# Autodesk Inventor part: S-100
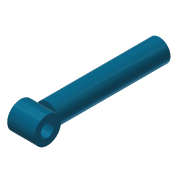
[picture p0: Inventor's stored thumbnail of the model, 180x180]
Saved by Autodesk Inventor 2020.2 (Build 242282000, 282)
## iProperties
Created: 2014-01
Part Number: S-100
Material: Ogólny
Document SubType Name: Modeling
Designer: F.Stasiak
Density: 1 g/cm^3
Appearance: Ciemnobłękitna
Manager: www.cadconsulting.pl
Company: Fabian Stasiak CAD Consulting
Author: F.Stasiak
Subject: Zbiór ćwiczeń. Autodesk Inventor 2020. Kurs podstawowy
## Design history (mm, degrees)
sketch "Szkic1"
  geometry: C1 r 25 at (0, 0); 1 further point
  constraints: 1 centre point, 1 coincident
  dimensions: "d0" = 50 diameter of C1
extrude "Wyciągnięcie proste1" new body sketch "Szkic1" distance "d1" = 250; taper "d2" = 0 deg
sketch "Szkic2"
  geometry: L1 (25, 250)-(-25, 250) reference; C1 r 30 at (0, 280); C2 r 15 at (0, 280); 2 further points
  constraints: 2 centre point, 1 coincident, 1 midpoint, 1 tangent, 1 vertical alignment
  dimensions: "d3" = 60 diameter of C1; "d4" = 30 diameter of C2
extrude "Wyciągnięcie proste2" join sketch "Szkic2" stored distance "d5" = 60; taper "d6" = 0 deg
sketch "Szkic3"
  geometry: C1 r 25 at (0, 0) reference; C2 r 15 at (0, 0)
  constraints: 1 centre point, 1 coincident
  dimensions: "d7" = 30 diameter of C2
extrude "Wyciągnięcie proste3" cut sketch "Szkic3" distance "d8" = 230; taper "d9" = 0 deg
node "Bryła1"
